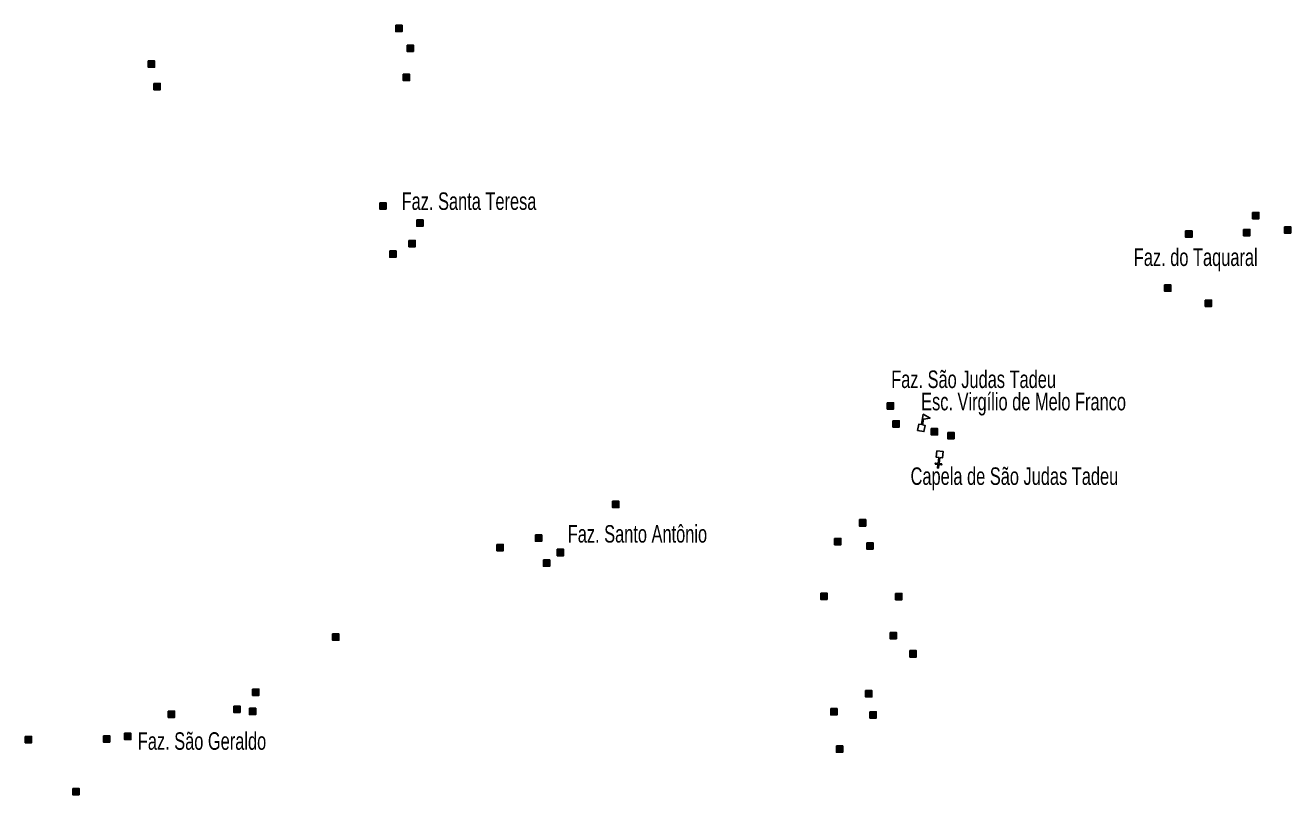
# Model space of a CAD drawing. Extents: x 265.7 to 292.1, y 7676.2 to 7704.2.
# Drawn here: x 280.09 to 285.87, y 7679.68 to 7683.19 of the extents above; entities that cross this region are included whole.
import ezdxf

# ---------------------------------------------------------------- set-up
doc = ezdxf.new("R2010")
doc.units = 0
doc.header["$LTSCALE"] = 0.032
for name, color, linetype, lineweight in [('2', 7, 'Continuous', 25), ('4', 7, 'Continuous', 25), ('6', 7, 'Continuous', 25)]:
    doc.layers.add(name, color=color, linetype=linetype, lineweight=lineweight)
doc.layers.add('61', color=7, linetype='Continuous')

msp = doc.modelspace()

# ---------------------------------------------------------------- hatches: boundary and pattern name
at = {"layer": '2'}
for points in [[(281.7807, 7683.1921), (281.8097, 7683.1921), (281.8097, 7683.1631), (281.7807, 7683.1631)], [(281.8323, 7683.1016), (281.8613, 7683.1016), (281.8613, 7683.0726), (281.8323, 7683.0726)], [(280.6493, 7683.029), (280.6783, 7683.029), (280.6783, 7683), (280.6493, 7683)], [(281.8153, 7682.9685), (281.8443, 7682.9685), (281.8443, 7682.9395), (281.8153, 7682.9395)], [(280.6751, 7682.9266), (280.7041, 7682.9266), (280.7041, 7682.8976), (280.6751, 7682.8976)], [(281.7073, 7682.3811), (281.7363, 7682.3811), (281.7363, 7682.3521), (281.7073, 7682.3521)], [(285.6973, 7682.3365), (285.7263, 7682.3365), (285.7263, 7682.3075), (285.6973, 7682.3075)], [(281.8767, 7682.3026), (281.9057, 7682.3026), (281.9057, 7682.2736), (281.8767, 7682.2736)], [(285.3914, 7682.2526), (285.4204, 7682.2526), (285.4204, 7682.2236), (285.3914, 7682.2236)], [(285.6562, 7682.259), (285.6852, 7682.259), (285.6852, 7682.23), (285.6562, 7682.23)], [(285.8425, 7682.2712), (285.8715, 7682.2712), (285.8715, 7682.2422), (285.8425, 7682.2422)], [(281.8412, 7682.2091), (281.8702, 7682.2091), (281.8702, 7682.1801), (281.8412, 7682.1801)], [(281.7532, 7682.1606), (281.7822, 7682.1606), (281.7822, 7682.1316), (281.7532, 7682.1316)], [(285.2949, 7682.0051), (285.3239, 7682.0051), (285.3239, 7681.9761), (285.2949, 7681.9761)], [(285.4811, 7681.9363), (285.5101, 7681.9363), (285.5101, 7681.9073), (285.4811, 7681.9073)], [(284.0275, 7681.4665), (284.0565, 7681.4665), (284.0565, 7681.4375), (284.0275, 7681.4375)], [(284.0533, 7681.3843), (284.0823, 7681.3843), (284.0823, 7681.3553), (284.0533, 7681.3553)], [(284.2286, 7681.3488), (284.2576, 7681.3488), (284.2576, 7681.3198), (284.2286, 7681.3198)], [(284.3036, 7681.3309), (284.3326, 7681.3309), (284.3326, 7681.3019), (284.3036, 7681.3019)], [(282.7717, 7681.0162), (282.8007, 7681.0162), (282.8007, 7680.9872), (282.7717, 7680.9872)], [(283.9, 7680.9323), (283.929, 7680.9323), (283.929, 7680.9033), (283.9, 7680.9033)], [(282.419, 7680.8629), (282.448, 7680.8629), (282.448, 7680.8339), (282.419, 7680.8339)], [(282.2431, 7680.8193), (282.2721, 7680.8193), (282.2721, 7680.7903), (282.2431, 7680.7903)], [(283.7869, 7680.8468), (283.8159, 7680.8468), (283.8159, 7680.8178), (283.7869, 7680.8178)], [(283.9338, 7680.8266), (283.9628, 7680.8266), (283.9628, 7680.7976), (283.9338, 7680.7976)], [(282.4554, 7680.7483), (282.4844, 7680.7483), (282.4844, 7680.7193), (282.4554, 7680.7193)], [(282.5192, 7680.7967), (282.5482, 7680.7967), (282.5482, 7680.7677), (282.5192, 7680.7677)], [(283.7233, 7680.5965), (283.7523, 7680.5965), (283.7523, 7680.5675), (283.7233, 7680.5675)], [(284.0654, 7680.5949), (284.0944, 7680.5949), (284.0944, 7680.5659), (284.0654, 7680.5659)], [(281.4918, 7680.4102), (281.5208, 7680.4102), (281.5208, 7680.3812), (281.4918, 7680.3812)], [(284.0405, 7680.4167), (284.0695, 7680.4167), (284.0695, 7680.3877), (284.0405, 7680.3877)], [(284.1308, 7680.3335), (284.1598, 7680.3335), (284.1598, 7680.3045), (284.1308, 7680.3045)], [(281.1261, 7680.1576), (281.1551, 7680.1576), (281.1551, 7680.1286), (281.1261, 7680.1286)], [(283.9283, 7680.1511), (283.9573, 7680.1511), (283.9573, 7680.1221), (283.9283, 7680.1221)], [(280.7412, 7680.0575), (280.7702, 7680.0575), (280.7702, 7680.0285), (280.7412, 7680.0285)], [(281.0399, 7680.08), (281.0689, 7680.08), (281.0689, 7680.051), (281.0399, 7680.051)], [(281.1116, 7680.0704), (281.1406, 7680.0704), (281.1406, 7680.0414), (281.1116, 7680.0414)], [(283.7693, 7680.0687), (283.7983, 7680.0687), (283.7983, 7680.0397), (283.7693, 7680.0397)], [(283.9484, 7680.0543), (283.9774, 7680.0543), (283.9774, 7680.0253), (283.9484, 7680.0253)], [(280.0875, 7679.9412), (280.1165, 7679.9412), (280.1165, 7679.9122), (280.0875, 7679.9122)], [(280.4442, 7679.9445), (280.4732, 7679.9445), (280.4732, 7679.9155), (280.4442, 7679.9155)], [(280.541, 7679.9558), (280.57, 7679.9558), (280.57, 7679.9268), (280.541, 7679.9268)], [(283.7951, 7679.8978), (283.8241, 7679.8978), (283.8241, 7679.8688), (283.7951, 7679.8688)], [(280.3046, 7679.7041), (280.3336, 7679.7041), (280.3336, 7679.6751), (280.3046, 7679.6751)]]:
    msp.add_hatch(color=256, dxfattribs=at).paths.add_polyline_path(points)

# ---------------------------------------------------------------- linework, layer by layer
for points in [[(281.7807, 7683.1921), (281.8097, 7683.1921), (281.8097, 7683.1631), (281.7807, 7683.1631)], [(281.8323, 7683.1016), (281.8613, 7683.1016), (281.8613, 7683.0726), (281.8323, 7683.0726)], [(280.6493, 7683.029), (280.6783, 7683.029), (280.6783, 7683), (280.6493, 7683)], [(281.8153, 7682.9685), (281.8443, 7682.9685), (281.8443, 7682.9395), (281.8153, 7682.9395)], [(280.6751, 7682.9266), (280.7041, 7682.9266), (280.7041, 7682.8976), (280.6751, 7682.8976)], [(281.7073, 7682.3811), (281.7363, 7682.3811), (281.7363, 7682.3521), (281.7073, 7682.3521)], [(285.6973, 7682.3365), (285.7263, 7682.3365), (285.7263, 7682.3075), (285.6973, 7682.3075)], [(281.8767, 7682.3026), (281.9057, 7682.3026), (281.9057, 7682.2736), (281.8767, 7682.2736)], [(285.3914, 7682.2526), (285.4204, 7682.2526), (285.4204, 7682.2236), (285.3914, 7682.2236)], [(285.6562, 7682.259), (285.6852, 7682.259), (285.6852, 7682.23), (285.6562, 7682.23)], [(285.8425, 7682.2712), (285.8715, 7682.2712), (285.8715, 7682.2422), (285.8425, 7682.2422)], [(281.8412, 7682.2091), (281.8702, 7682.2091), (281.8702, 7682.1801), (281.8412, 7682.1801)], [(281.7532, 7682.1606), (281.7822, 7682.1606), (281.7822, 7682.1316), (281.7532, 7682.1316)], [(285.2949, 7682.0051), (285.3239, 7682.0051), (285.3239, 7681.9761), (285.2949, 7681.9761)], [(285.4811, 7681.9363), (285.5101, 7681.9363), (285.5101, 7681.9073), (285.4811, 7681.9073)], [(284.0275, 7681.4665), (284.0565, 7681.4665), (284.0565, 7681.4375), (284.0275, 7681.4375)], [(284.0533, 7681.3843), (284.0823, 7681.3843), (284.0823, 7681.3553), (284.0533, 7681.3553)], [(284.2286, 7681.3488), (284.2576, 7681.3488), (284.2576, 7681.3198), (284.2286, 7681.3198)], [(284.3036, 7681.3309), (284.3326, 7681.3309), (284.3326, 7681.3019), (284.3036, 7681.3019)], [(282.7717, 7681.0162), (282.8007, 7681.0162), (282.8007, 7680.9872), (282.7717, 7680.9872)], [(283.9, 7680.9323), (283.929, 7680.9323), (283.929, 7680.9033), (283.9, 7680.9033)], [(282.419, 7680.8629), (282.448, 7680.8629), (282.448, 7680.8339), (282.419, 7680.8339)], [(282.2431, 7680.8193), (282.2721, 7680.8193), (282.2721, 7680.7903), (282.2431, 7680.7903)], [(283.7869, 7680.8468), (283.8159, 7680.8468), (283.8159, 7680.8178), (283.7869, 7680.8178)], [(283.9338, 7680.8266), (283.9628, 7680.8266), (283.9628, 7680.7976), (283.9338, 7680.7976)], [(282.4554, 7680.7483), (282.4844, 7680.7483), (282.4844, 7680.7193), (282.4554, 7680.7193)], [(282.5192, 7680.7967), (282.5482, 7680.7967), (282.5482, 7680.7677), (282.5192, 7680.7677)], [(283.7233, 7680.5965), (283.7523, 7680.5965), (283.7523, 7680.5675), (283.7233, 7680.5675)], [(284.0654, 7680.5949), (284.0944, 7680.5949), (284.0944, 7680.5659), (284.0654, 7680.5659)], [(281.4918, 7680.4102), (281.5208, 7680.4102), (281.5208, 7680.3812), (281.4918, 7680.3812)], [(284.0405, 7680.4167), (284.0695, 7680.4167), (284.0695, 7680.3877), (284.0405, 7680.3877)], [(284.1308, 7680.3335), (284.1598, 7680.3335), (284.1598, 7680.3045), (284.1308, 7680.3045)], [(281.1261, 7680.1576), (281.1551, 7680.1576), (281.1551, 7680.1286), (281.1261, 7680.1286)], [(283.9283, 7680.1511), (283.9573, 7680.1511), (283.9573, 7680.1221), (283.9283, 7680.1221)], [(280.7412, 7680.0575), (280.7702, 7680.0575), (280.7702, 7680.0285), (280.7412, 7680.0285)], [(281.0399, 7680.08), (281.0689, 7680.08), (281.0689, 7680.051), (281.0399, 7680.051)], [(281.1116, 7680.0704), (281.1406, 7680.0704), (281.1406, 7680.0414), (281.1116, 7680.0414)], [(283.7693, 7680.0687), (283.7983, 7680.0687), (283.7983, 7680.0397), (283.7693, 7680.0397)], [(283.9484, 7680.0543), (283.9774, 7680.0543), (283.9774, 7680.0253), (283.9484, 7680.0253)], [(280.0875, 7679.9412), (280.1165, 7679.9412), (280.1165, 7679.9122), (280.0875, 7679.9122)], [(280.4442, 7679.9445), (280.4732, 7679.9445), (280.4732, 7679.9155), (280.4442, 7679.9155)], [(280.541, 7679.9558), (280.57, 7679.9558), (280.57, 7679.9268), (280.541, 7679.9268)], [(283.7951, 7679.8978), (283.8241, 7679.8978), (283.8241, 7679.8688), (283.7951, 7679.8688)], [(280.3046, 7679.7041), (280.3336, 7679.7041), (280.3336, 7679.6751), (280.3046, 7679.6751)]]:
    msp.add_lwpolyline(points, close=True, dxfattribs=at)
at = {"layer": '4'}
for points in [[(284.1833, 7681.3666), (284.1921, 7681.4141), (284.2233, 7681.3966), (284.1928, 7681.3913), (284.1881, 7681.3656)], [(284.1881, 7681.3656), (284.2, 7681.3635), (284.1948, 7681.3349), (284.1663, 7681.3402), (284.1715, 7681.3687), (284.1833, 7681.3666)]]:
    msp.add_lwpolyline(points, dxfattribs=at)
at = {"layer": '6'}
for points in [[(284.2676, 7681.2161), (284.2644, 7681.1892), (284.2764, 7681.1877), (284.2758, 7681.1828), (284.2638, 7681.1843), (284.2618, 7681.168), (284.257, 7681.1686), (284.259, 7681.1849), (284.247, 7681.1863), (284.2476, 7681.1912), (284.2596, 7681.1897), (284.2629, 7681.2166)], [(284.2629, 7681.2166), (284.2508, 7681.2181), (284.2543, 7681.2469), (284.2831, 7681.2434), (284.2796, 7681.2146), (284.2676, 7681.2161)]]:
    msp.add_lwpolyline(points, dxfattribs=at)

# ---------------------------------------------------------------- texts
at = {"layer": '61', "width": 0.7}
for s, p in [('Faz. Santa Teresa', (281.8077, 7682.3482)), ('Faz. do Taquaral', (285.1544, 7682.092)), ('Faz. São Judas Tadeu', (284.0453, 7681.5341)), ('Esc. Virgílio de Melo Franco', (284.1823, 7681.4321)), ('Capela de São Judas Tadeu', (284.134, 7681.0912)), ('Faz. Santo Antônio', (282.567, 7680.8275)), ('Faz. São Geraldo', (280.6017, 7679.8804))]:
    msp.add_text(s, height=0.08, dxfattribs=at).set_placement(p)

doc.saveas('drawing.dxf')
